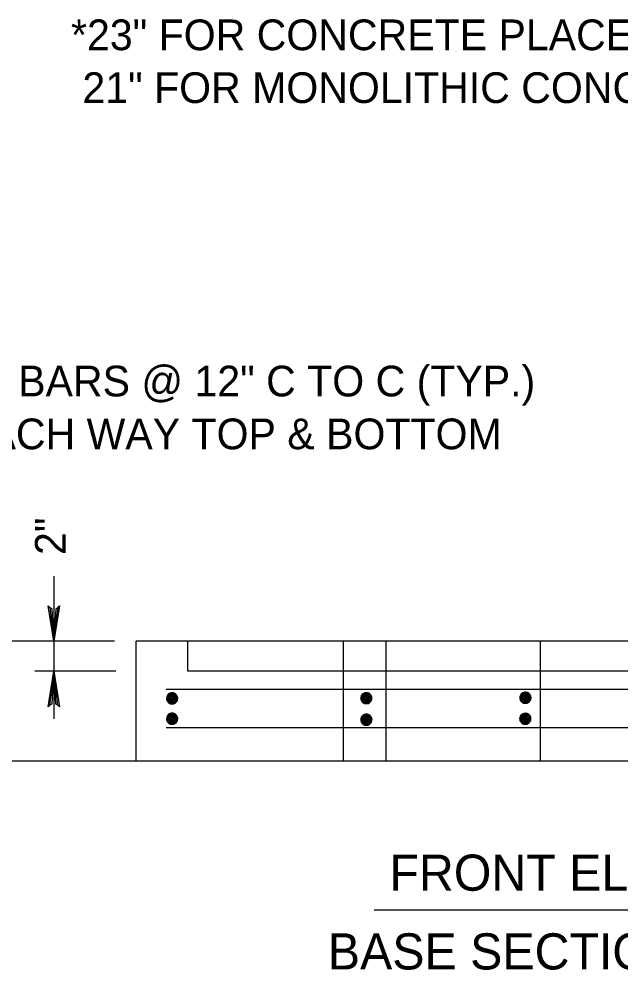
# Model space of a CAD drawing. Extents: x 638877 to 639960, y 297341 to 299123.
# Drawn here: x 638950.9 to 639009.8, y 297559.4 to 297652.3 of the extents above; entities that cross this region are included whole.
import ezdxf

# ---------------------------------------------------------------- set-up
doc = ezdxf.new("R2010")
doc.units = 0
doc.layers.add('2', color=7, linetype='Continuous')
doc.layers.add('3', color=7, linetype='Continuous')

msp = doc.modelspace()

# ---------------------------------------------------------------- linework, layer by layer
at = {"layer": '2'}
for p, q in [((638954.356, 297597.865), (638954.356, 297591.516)), ((638960.269, 297591.516), (638945.55, 297591.516)), ((638954.356, 297591.516), (638954.356, 297583.947)), ((638962.396, 297579.816), (638962.396, 297591.516)), ((638967.46, 297591.516), (638962.396, 297591.516)), ((639061.752, 297591.516), (638967.46, 297591.516)), ((638967.46, 297588.588), (638967.46, 297591.516)), ((638982.66, 297579.816), (638982.66, 297591.516)), ((638986.843, 297579.816), (638986.843, 297591.516)), ((639001.9, 297579.816), (639001.9, 297591.516)), ((638960.404, 297588.588), (638952.5, 297588.588)), ((639061.752, 297588.588), (638967.46, 297588.588)), ((639064.318, 297586.823), (638965.315, 297586.823)), ((639064.318, 297583.068), (638965.315, 297583.068)), ((638962.396, 297579.816), (638945.55, 297579.816)), ((639066.822, 297579.816), (638962.396, 297579.816))]:
    msp.add_line(p, q, dxfattribs=at)
for points in [[(638954.772, 297594.82), (638954.533, 297594.698), (638954.356, 297591.516), (638954.772, 297594.82), (638954.915, 297594.992), (638954.356, 297591.516), (638954.2, 297594.696), (638953.961, 297594.813), (638954.356, 297591.516), (638953.805, 297594.992), (638953.961, 297594.813)], [(638953.94, 297585.284), (638954.18, 297585.406), (638954.356, 297588.588), (638953.94, 297585.284), (638953.797, 297585.112), (638954.356, 297588.588), (638954.512, 297585.408), (638954.752, 297585.291), (638954.356, 297588.588), (638954.908, 297585.112), (638954.752, 297585.291)]]:
    msp.add_lwpolyline(points, dxfattribs=at)
for points in [[(638965.906, 297585.943), (638965.962, 297585.909), (638965.958, 297585.86), (638965.872, 297585.857), (638965.831, 297585.935), (638965.872, 297586.029), (638965.958, 297586.025), (638966.007, 297585.973), (638966.015, 297585.86), (638965.962, 297585.789), (638965.876, 297585.752), (638965.767, 297585.808), (638965.745, 297585.92), (638965.779, 297586.055), (638965.854, 297586.126), (638965.985, 297586.119), (638966.067, 297586.051), (638966.093, 297585.935), (638966.074, 297585.83), (638966.026, 297585.744), (638965.943, 297585.703), (638965.839, 297585.681), (638965.738, 297585.711), (638965.67, 297585.812), (638965.644, 297585.969), (638965.708, 297586.137), (638965.816, 297586.224), (638965.962, 297586.224), (638966.086, 297586.167), (638966.172, 297586.051), (638966.179, 297585.86), (638966.112, 297585.729), (638965.996, 297585.647), (638965.872, 297585.602), (638965.73, 297585.621), (638965.625, 297585.729), (638965.565, 297585.887), (638965.603, 297586.134), (638965.726, 297586.287), (638965.898, 297586.321), (638966.067, 297586.287), (638966.198, 297586.186), (638966.247, 297586.04), (638966.243, 297585.812), (638966.146, 297585.636), (638966.015, 297585.55), (638965.869, 297585.527), (638965.745, 297585.546), (638965.606, 297585.598), (638965.509, 297585.744), (638965.487, 297585.98), (638965.535, 297586.19), (638965.666, 297586.343), (638965.824, 297586.407), (638966.018, 297586.388), (638966.202, 297586.321), (638966.284, 297586.205), (638966.348, 297585.995), (638966.322, 297585.782), (638966.258, 297585.625), (638966.142, 297585.512), (638966.011, 297585.452), (638965.872, 297585.452), (638965.73, 297585.456), (638965.591, 297585.497), (638965.509, 297585.572), (638965.442, 297585.688), (638965.408, 297585.808), (638965.386, 297585.92), (638965.412, 297586.074), (638965.453, 297586.224), (638965.539, 297586.355), (638965.655, 297586.444), (638965.794, 297586.489), (638965.928, 297586.512), (638966.074, 297586.478), (638966.198, 297586.418), (638966.307, 297586.313), (638966.381, 297586.186), (638966.423, 297586.051), (638966.43, 297585.898), (638966.393, 297585.722), (638966.307, 297585.572), (638966.22, 297585.479), (638966.108, 297585.404), (638965.988, 297585.377), (638965.816, 297585.377), (638965.767, 297585.381), (638965.636, 297585.452), (638965.532, 297585.546)], [(638984.885, 297585.96), (638984.941, 297585.926), (638984.938, 297585.878), (638984.852, 297585.874), (638984.81, 297585.953), (638984.852, 297586.046), (638984.938, 297586.042), (638984.986, 297585.99), (638984.994, 297585.878), (638984.941, 297585.807), (638984.855, 297585.769), (638984.747, 297585.825), (638984.724, 297585.938), (638984.758, 297586.072), (638984.833, 297586.144), (638984.964, 297586.136), (638985.046, 297586.069), (638985.072, 297585.953), (638985.054, 297585.848), (638985.005, 297585.762), (638984.923, 297585.72), (638984.818, 297585.698), (638984.717, 297585.728), (638984.649, 297585.829), (638984.623, 297585.986), (638984.687, 297586.155), (638984.795, 297586.241), (638984.941, 297586.241), (638985.065, 297586.185), (638985.151, 297586.069), (638985.159, 297585.878), (638985.091, 297585.747), (638984.975, 297585.664), (638984.852, 297585.619), (638984.709, 297585.638), (638984.604, 297585.747), (638984.544, 297585.904), (638984.582, 297586.151), (638984.705, 297586.305), (638984.878, 297586.338), (638985.046, 297586.305), (638985.177, 297586.203), (638985.226, 297586.057), (638985.222, 297585.829), (638985.125, 297585.653), (638984.994, 297585.567), (638984.848, 297585.545), (638984.724, 297585.563), (638984.586, 297585.616), (638984.488, 297585.762), (638984.466, 297585.998), (638984.515, 297586.207), (638984.646, 297586.361), (638984.803, 297586.424), (638984.998, 297586.406), (638985.181, 297586.338), (638985.263, 297586.222), (638985.327, 297586.013), (638985.301, 297585.799), (638985.237, 297585.642), (638985.121, 297585.53), (638984.99, 297585.47), (638984.852, 297585.47), (638984.709, 297585.473), (638984.571, 297585.515), (638984.488, 297585.589), (638984.421, 297585.706), (638984.387, 297585.825), (638984.365, 297585.938), (638984.391, 297586.091), (638984.432, 297586.241), (638984.518, 297586.372), (638984.634, 297586.462), (638984.773, 297586.507), (638984.908, 297586.529), (638985.054, 297586.495), (638985.177, 297586.436), (638985.286, 297586.331), (638985.361, 297586.203), (638985.402, 297586.069), (638985.409, 297585.915), (638985.372, 297585.739), (638985.286, 297585.589), (638985.2, 297585.496), (638985.087, 297585.421), (638984.968, 297585.395), (638984.795, 297585.395), (638984.747, 297585.399), (638984.616, 297585.47), (638984.511, 297585.563)], [(639000.428, 297586.004), (639000.484, 297585.97), (639000.481, 297585.921), (639000.394, 297585.918), (639000.353, 297585.996), (639000.394, 297586.09), (639000.481, 297586.086), (639000.529, 297586.034), (639000.537, 297585.921), (639000.484, 297585.85), (639000.398, 297585.813), (639000.29, 297585.869), (639000.267, 297585.981), (639000.301, 297586.116), (639000.376, 297586.187), (639000.507, 297586.18), (639000.589, 297586.112), (639000.615, 297585.996), (639000.597, 297585.892), (639000.548, 297585.805), (639000.466, 297585.764), (639000.361, 297585.742), (639000.26, 297585.772), (639000.192, 297585.873), (639000.166, 297586.03), (639000.23, 297586.199), (639000.338, 297586.285), (639000.484, 297586.285), (639000.608, 297586.228), (639000.694, 297586.112), (639000.701, 297585.921), (639000.634, 297585.79), (639000.518, 297585.708), (639000.394, 297585.663), (639000.252, 297585.682), (639000.147, 297585.79), (639000.087, 297585.948), (639000.125, 297586.195), (639000.248, 297586.348), (639000.421, 297586.382), (639000.589, 297586.348), (639000.72, 297586.247), (639000.769, 297586.101), (639000.765, 297585.873), (639000.668, 297585.697), (639000.537, 297585.611), (639000.391, 297585.588), (639000.267, 297585.607), (639000.129, 297585.659), (639000.031, 297585.805), (639000.009, 297586.041), (639000.057, 297586.251), (639000.189, 297586.404), (639000.346, 297586.468), (639000.54, 297586.449), (639000.724, 297586.382), (639000.806, 297586.266), (639000.87, 297586.056), (639000.844, 297585.843), (639000.78, 297585.686), (639000.664, 297585.573), (639000.533, 297585.513), (639000.394, 297585.513), (639000.252, 297585.517), (639000.114, 297585.558), (639000.031, 297585.633), (638999.964, 297585.749), (638999.93, 297585.869), (638999.908, 297585.981), (638999.934, 297586.135), (638999.975, 297586.285), (639000.061, 297586.416), (639000.177, 297586.506), (639000.316, 297586.55), (639000.451, 297586.573), (639000.597, 297586.539), (639000.72, 297586.479), (639000.829, 297586.374), (639000.904, 297586.247), (639000.945, 297586.112), (639000.952, 297585.959), (639000.915, 297585.783), (639000.829, 297585.633), (639000.743, 297585.54), (639000.63, 297585.465), (639000.511, 297585.438), (639000.338, 297585.438), (639000.29, 297585.442), (639000.159, 297585.513), (639000.054, 297585.607)], [(638965.906, 297583.956), (638965.963, 297583.922), (638965.959, 297583.873), (638965.873, 297583.87), (638965.832, 297583.948), (638965.873, 297584.042), (638965.959, 297584.038), (638966.008, 297583.986), (638966.015, 297583.873), (638965.963, 297583.802), (638965.876, 297583.765), (638965.768, 297583.821), (638965.745, 297583.933), (638965.779, 297584.068), (638965.854, 297584.139), (638965.985, 297584.132), (638966.067, 297584.064), (638966.094, 297583.948), (638966.075, 297583.843), (638966.026, 297583.757), (638965.944, 297583.716), (638965.839, 297583.694), (638965.738, 297583.724), (638965.671, 297583.825), (638965.644, 297583.982), (638965.708, 297584.15), (638965.817, 297584.237), (638965.963, 297584.237), (638966.086, 297584.18), (638966.172, 297584.064), (638966.18, 297583.873), (638966.112, 297583.742), (638965.996, 297583.66), (638965.873, 297583.615), (638965.73, 297583.634), (638965.626, 297583.742), (638965.566, 297583.9), (638965.603, 297584.147), (638965.727, 297584.3), (638965.899, 297584.334), (638966.067, 297584.3), (638966.198, 297584.199), (638966.247, 297584.053), (638966.243, 297583.825), (638966.146, 297583.649), (638966.015, 297583.563), (638965.869, 297583.54), (638965.745, 297583.559), (638965.607, 297583.611), (638965.51, 297583.757), (638965.487, 297583.993), (638965.536, 297584.203), (638965.667, 297584.356), (638965.824, 297584.42), (638966.019, 297584.401), (638966.202, 297584.334), (638966.285, 297584.218), (638966.348, 297584.008), (638966.322, 297583.795), (638966.258, 297583.638), (638966.142, 297583.525), (638966.011, 297583.465), (638965.873, 297583.465), (638965.73, 297583.469), (638965.592, 297583.51), (638965.51, 297583.585), (638965.442, 297583.701), (638965.408, 297583.821), (638965.386, 297583.933), (638965.412, 297584.087), (638965.453, 297584.237), (638965.54, 297584.368), (638965.656, 297584.457), (638965.794, 297584.502), (638965.929, 297584.525), (638966.075, 297584.491), (638966.198, 297584.431), (638966.307, 297584.326), (638966.382, 297584.199), (638966.423, 297584.064), (638966.431, 297583.911), (638966.393, 297583.735), (638966.307, 297583.585), (638966.221, 297583.491), (638966.109, 297583.417), (638965.989, 297583.39), (638965.817, 297583.39), (638965.768, 297583.394), (638965.637, 297583.465), (638965.532, 297583.559)], [(638984.885, 297583.864), (638984.941, 297583.83), (638984.937, 297583.781), (638984.851, 297583.778), (638984.81, 297583.856), (638984.851, 297583.95), (638984.937, 297583.946), (638984.986, 297583.894), (638984.993, 297583.781), (638984.941, 297583.71), (638984.855, 297583.673), (638984.746, 297583.729), (638984.724, 297583.841), (638984.758, 297583.976), (638984.832, 297584.047), (638984.964, 297584.04), (638985.046, 297583.972), (638985.072, 297583.856), (638985.053, 297583.751), (638985.005, 297583.665), (638984.922, 297583.624), (638984.817, 297583.602), (638984.716, 297583.632), (638984.649, 297583.733), (638984.623, 297583.89), (638984.686, 297584.058), (638984.795, 297584.145), (638984.941, 297584.145), (638985.065, 297584.088), (638985.151, 297583.972), (638985.158, 297583.781), (638985.091, 297583.65), (638984.975, 297583.568), (638984.851, 297583.523), (638984.709, 297583.542), (638984.604, 297583.65), (638984.544, 297583.808), (638984.582, 297584.055), (638984.705, 297584.208), (638984.877, 297584.242), (638985.046, 297584.208), (638985.177, 297584.107), (638985.226, 297583.961), (638985.222, 297583.733), (638985.124, 297583.557), (638984.993, 297583.471), (638984.847, 297583.448), (638984.724, 297583.467), (638984.585, 297583.519), (638984.488, 297583.665), (638984.466, 297583.901), (638984.514, 297584.111), (638984.645, 297584.264), (638984.803, 297584.328), (638984.997, 297584.309), (638985.181, 297584.242), (638985.263, 297584.126), (638985.327, 297583.916), (638985.3, 297583.703), (638985.237, 297583.546), (638985.121, 297583.433), (638984.99, 297583.373), (638984.851, 297583.373), (638984.709, 297583.377), (638984.57, 297583.418), (638984.488, 297583.493), (638984.421, 297583.609), (638984.387, 297583.729), (638984.364, 297583.841), (638984.391, 297583.995), (638984.432, 297584.145), (638984.518, 297584.276), (638984.634, 297584.365), (638984.773, 297584.41), (638984.907, 297584.433), (638985.053, 297584.399), (638985.177, 297584.339), (638985.285, 297584.234), (638985.36, 297584.107), (638985.402, 297583.972), (638985.409, 297583.819), (638985.372, 297583.643), (638985.285, 297583.493), (638985.199, 297583.399), (638985.087, 297583.325), (638984.967, 297583.298), (638984.795, 297583.298), (638984.746, 297583.302), (638984.615, 297583.373), (638984.51, 297583.467)], [(639000.418, 297583.95), (639000.474, 297583.917), (639000.47, 297583.868), (639000.384, 297583.864), (639000.343, 297583.943), (639000.384, 297584.037), (639000.47, 297584.033), (639000.519, 297583.98), (639000.526, 297583.868), (639000.474, 297583.797), (639000.388, 297583.76), (639000.279, 297583.816), (639000.257, 297583.928), (639000.29, 297584.063), (639000.365, 297584.134), (639000.496, 297584.126), (639000.579, 297584.059), (639000.605, 297583.943), (639000.586, 297583.838), (639000.537, 297583.752), (639000.455, 297583.711), (639000.35, 297583.688), (639000.249, 297583.718), (639000.182, 297583.819), (639000.156, 297583.977), (639000.219, 297584.145), (639000.328, 297584.231), (639000.474, 297584.231), (639000.597, 297584.175), (639000.683, 297584.059), (639000.691, 297583.868), (639000.624, 297583.737), (639000.507, 297583.655), (639000.384, 297583.61), (639000.242, 297583.628), (639000.137, 297583.737), (639000.077, 297583.894), (639000.114, 297584.141), (639000.238, 297584.295), (639000.41, 297584.329), (639000.579, 297584.295), (639000.71, 297584.194), (639000.758, 297584.048), (639000.755, 297583.819), (639000.657, 297583.643), (639000.526, 297583.557), (639000.38, 297583.535), (639000.257, 297583.554), (639000.118, 297583.606), (639000.021, 297583.752), (638999.998, 297583.988), (639000.047, 297584.198), (639000.178, 297584.351), (639000.335, 297584.415), (639000.53, 297584.396), (639000.713, 297584.329), (639000.796, 297584.213), (639000.859, 297584.003), (639000.833, 297583.789), (639000.77, 297583.632), (639000.653, 297583.52), (639000.522, 297583.46), (639000.384, 297583.46), (639000.242, 297583.464), (639000.103, 297583.505), (639000.021, 297583.58), (638999.953, 297583.696), (638999.92, 297583.816), (638999.897, 297583.928), (638999.923, 297584.081), (638999.965, 297584.231), (639000.051, 297584.362), (639000.167, 297584.452), (639000.305, 297584.497), (639000.44, 297584.52), (639000.586, 297584.486), (639000.71, 297584.426), (639000.818, 297584.321), (639000.893, 297584.194), (639000.934, 297584.059), (639000.942, 297583.906), (639000.904, 297583.73), (639000.818, 297583.58), (639000.732, 297583.486), (639000.62, 297583.411), (639000.5, 297583.385), (639000.328, 297583.385), (639000.279, 297583.389), (639000.148, 297583.46), (639000.043, 297583.554)]]:
    msp.add_spline(points, degree=3, dxfattribs=at)
at = {"layer": '3'}
msp.add_line((638985.643, 297565.301), (639058.146, 297565.301), dxfattribs=at)

# ---------------------------------------------------------------- texts
for s, height, p in [('*23" FOR CONCRETE PLACEMENT WITH DEPRESSED KEY', 2.99988, (638956.032, 297649.259)), (' 21" FOR MONOLITHIC CONCRETE PLACEMENT', 2.99988, (638956.032, 297644.099)), ('#4 BARS @ 12" C TO C (TYP.)', 2.99988, (638945.294, 297615.438)), ('EACH WAY TOP & BOTTOM', 2.99988, (638945.294, 297610.278)), ('FRONT ELEVATION VIEW', 3.52986, (638987.145, 297567.152)), ('BASE SECTION FOR TYPE D-W', 3.52986, (638981.128, 297559.461))]:
    msp.add_text(s, height=height, dxfattribs=at).set_placement(p)
msp.add_text('2"', height=2.9999, rotation=90, dxfattribs=at).set_placement((638955.511, 297599.95))

doc.saveas('drawing.dxf')
